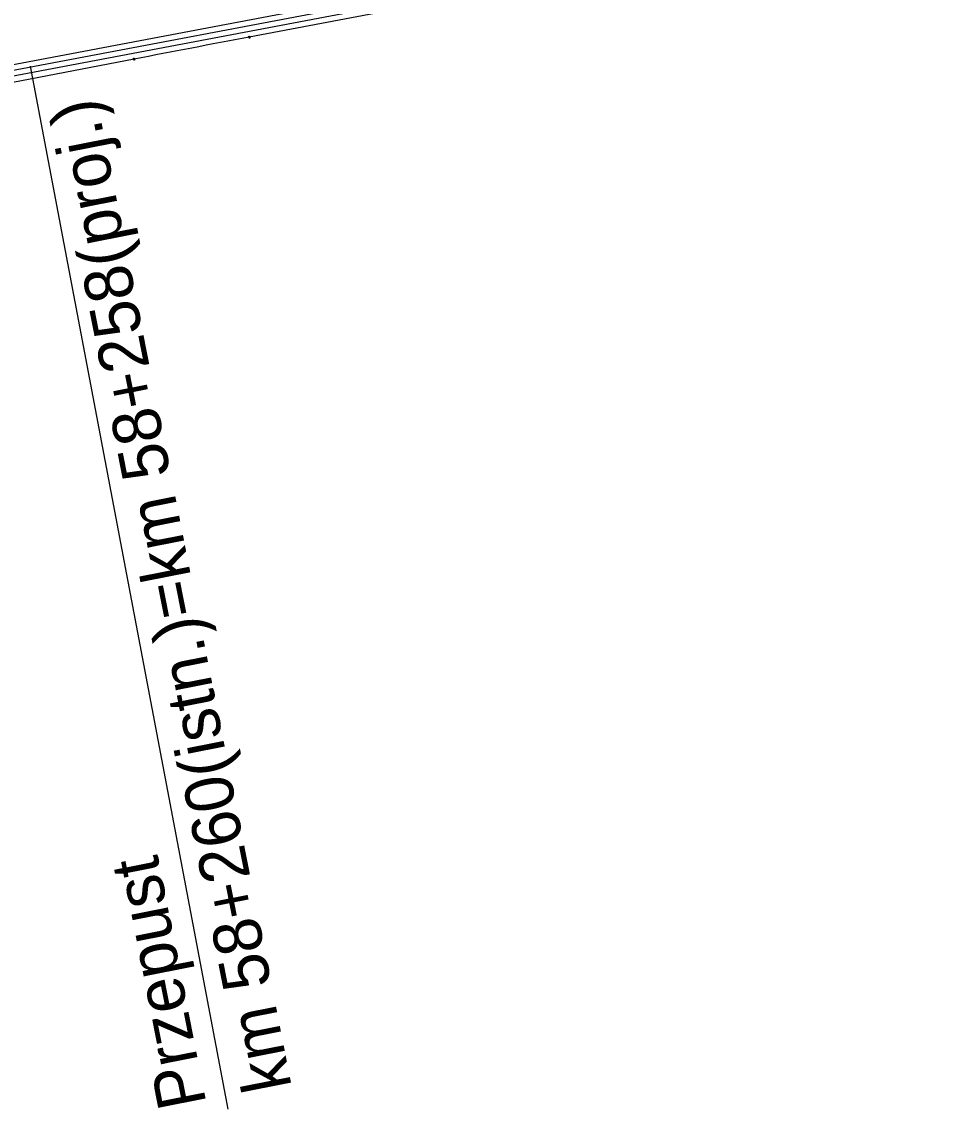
# Model space of a CAD drawing. Extents: x 6540402 to 6566579, y 5525343 to 5532423.
# Drawn here: x 6560773 to 6561436, y 5528558 to 5529347 of the extents above; entities that cross this region are included whole.
import ezdxf

# ---------------------------------------------------------------- set-up
doc = ezdxf.new("R2010")
doc.units = 0
for name, color, linetype in [('IR_ps_geometria', 7, 'Continuous'), ('TOR_PS_OPIS_T-opisy dodatkowe', 7, 'Continuous'), ('TOR_PS_T-tory projektowane', 7, 'Continuous')]:
    doc.layers.add(name, color=color, linetype=linetype)

msp = doc.modelspace()

# ---------------------------------------------------------------- linework, layer by layer
at = {"layer": 'IR_ps_geometria'}
for points in [[(6560937.83, 5529335.95), (6560937.87, 5529335.71), (6560937.9, 5529335.71), (6560937.94, 5529335.71), (6560937.97, 5529335.7), (6560938, 5529335.7), (6560938.03, 5529335.68), (6560938.06, 5529335.67), (6560938.09, 5529335.65), (6560938.11, 5529335.62), (6560938.13, 5529335.6), (6560938.14, 5529335.57), (6560938.16, 5529335.54), (6560938.16, 5529335.51), (6560938.17, 5529335.47), (6560938.17, 5529335.44), (6560938.16, 5529335.41), (6560938.15, 5529335.38), (6560938.14, 5529335.35), (6560938.13, 5529335.32), (6560938.1, 5529335.29), (6560938.08, 5529335.27), (6560938.06, 5529335.25), (6560938.03, 5529335.23), (6560938, 5529335.22), (6560937.97, 5529335.21), (6560937.93, 5529335.21), (6560937.9, 5529335.21), (6560937.87, 5529335.22), (6560937.84, 5529335.22), (6560937.81, 5529335.24), (6560937.78, 5529335.25), (6560937.75, 5529335.27), (6560937.73, 5529335.3), (6560937.71, 5529335.32), (6560937.69, 5529335.35), (6560937.68, 5529335.38), (6560937.67, 5529335.41), (6560937.67, 5529335.45), (6560937.67, 5529335.48), (6560937.67, 5529335.51), (6560937.68, 5529335.54), (6560937.7, 5529335.57), (6560937.71, 5529335.6), (6560937.73, 5529335.63), (6560937.76, 5529335.65), (6560937.78, 5529335.67), (6560937.81, 5529335.69), (6560937.84, 5529335.7), (6560937.87, 5529335.71), (6560937.78, 5529336.2), (6560937.75, 5529336.19), (6560937.71, 5529336.19), (6560937.68, 5529336.2), (6560937.65, 5529336.21), (6560937.62, 5529336.22), (6560937.59, 5529336.24), (6560937.57, 5529336.26), (6560937.54, 5529336.28), (6560937.52, 5529336.31), (6560937.51, 5529336.33), (6560937.49, 5529336.36), (6560937.49, 5529336.4), (6560937.48, 5529336.43), (6560937.48, 5529336.46), (6560937.49, 5529336.49), (6560937.5, 5529336.52), (6560937.51, 5529336.55), (6560937.53, 5529336.58), (6560937.55, 5529336.61), (6560937.57, 5529336.63), (6560937.6, 5529336.65), (6560937.62, 5529336.67), (6560937.65, 5529336.68), (6560937.69, 5529336.69), (6560937.72, 5529336.69), (6560937.75, 5529336.69), (6560937.78, 5529336.69), (6560937.81, 5529336.68), (6560937.84, 5529336.67), (6560937.87, 5529336.65), (6560937.9, 5529336.63), (6560937.92, 5529336.61), (6560937.94, 5529336.58), (6560937.96, 5529336.55), (6560937.97, 5529336.52), (6560937.98, 5529336.49), (6560937.98, 5529336.46), (6560937.98, 5529336.42), (6560937.98, 5529336.39), (6560937.97, 5529336.36), (6560937.96, 5529336.33), (6560937.94, 5529336.3), (6560937.92, 5529336.28), (6560937.9, 5529336.25), (6560937.87, 5529336.23), (6560937.84, 5529336.22), (6560937.81, 5529336.2), (6560937.78, 5529336.2)], [(6560937.83, 5529335.95), (6560937.87, 5529335.71), (6560937.9, 5529335.71), (6560937.94, 5529335.71), (6560937.97, 5529335.7), (6560938, 5529335.7), (6560938.03, 5529335.68), (6560938.06, 5529335.67), (6560938.09, 5529335.65), (6560938.11, 5529335.62), (6560938.13, 5529335.6), (6560938.14, 5529335.57), (6560938.16, 5529335.54), (6560938.16, 5529335.51), (6560938.17, 5529335.47), (6560938.17, 5529335.44), (6560938.16, 5529335.41), (6560938.15, 5529335.38), (6560938.14, 5529335.35), (6560938.13, 5529335.32), (6560938.1, 5529335.29), (6560938.08, 5529335.27), (6560938.06, 5529335.25), (6560938.03, 5529335.23), (6560938, 5529335.22), (6560937.97, 5529335.21), (6560937.93, 5529335.21), (6560937.9, 5529335.21), (6560937.87, 5529335.22), (6560937.84, 5529335.22), (6560937.81, 5529335.24), (6560937.78, 5529335.25), (6560937.75, 5529335.27), (6560937.73, 5529335.3), (6560937.71, 5529335.32), (6560937.69, 5529335.35), (6560937.68, 5529335.38), (6560937.67, 5529335.41), (6560937.67, 5529335.45), (6560937.67, 5529335.48), (6560937.67, 5529335.51), (6560937.68, 5529335.54), (6560937.7, 5529335.57), (6560937.71, 5529335.6), (6560937.73, 5529335.63), (6560937.76, 5529335.65), (6560937.78, 5529335.67), (6560937.81, 5529335.69), (6560937.84, 5529335.7), (6560937.87, 5529335.71), (6560937.78, 5529336.2), (6560937.75, 5529336.19), (6560937.71, 5529336.19), (6560937.68, 5529336.2), (6560937.65, 5529336.21), (6560937.62, 5529336.22), (6560937.59, 5529336.24), (6560937.57, 5529336.26), (6560937.54, 5529336.28), (6560937.52, 5529336.31), (6560937.51, 5529336.33), (6560937.49, 5529336.36), (6560937.49, 5529336.4), (6560937.48, 5529336.43), (6560937.48, 5529336.46), (6560937.49, 5529336.49), (6560937.5, 5529336.52), (6560937.51, 5529336.55), (6560937.53, 5529336.58), (6560937.55, 5529336.61), (6560937.57, 5529336.63), (6560937.6, 5529336.65), (6560937.62, 5529336.67), (6560937.65, 5529336.68), (6560937.69, 5529336.69), (6560937.72, 5529336.69), (6560937.75, 5529336.69), (6560937.78, 5529336.69), (6560937.81, 5529336.68), (6560937.84, 5529336.67), (6560937.87, 5529336.65), (6560937.9, 5529336.63), (6560937.92, 5529336.61), (6560937.94, 5529336.58), (6560937.96, 5529336.55), (6560937.97, 5529336.52), (6560937.98, 5529336.49), (6560937.98, 5529336.46), (6560937.98, 5529336.42), (6560937.98, 5529336.39), (6560937.97, 5529336.36), (6560937.96, 5529336.33), (6560937.94, 5529336.3), (6560937.92, 5529336.28), (6560937.9, 5529336.25), (6560937.87, 5529336.23), (6560937.84, 5529336.22), (6560937.81, 5529336.2), (6560937.78, 5529336.2)], [(6560937.83, 5529335.95), (6560937.87, 5529335.71), (6560937.9, 5529335.71), (6560937.94, 5529335.71), (6560937.97, 5529335.7), (6560938, 5529335.7), (6560938.03, 5529335.68), (6560938.06, 5529335.67), (6560938.09, 5529335.65), (6560938.11, 5529335.62), (6560938.13, 5529335.6), (6560938.14, 5529335.57), (6560938.16, 5529335.54), (6560938.16, 5529335.51), (6560938.17, 5529335.47), (6560938.17, 5529335.44), (6560938.16, 5529335.41), (6560938.15, 5529335.38), (6560938.14, 5529335.35), (6560938.13, 5529335.32), (6560938.1, 5529335.29), (6560938.08, 5529335.27), (6560938.06, 5529335.25), (6560938.03, 5529335.23), (6560938, 5529335.22), (6560937.97, 5529335.21), (6560937.93, 5529335.21), (6560937.9, 5529335.21), (6560937.87, 5529335.22), (6560937.84, 5529335.22), (6560937.81, 5529335.24), (6560937.78, 5529335.25), (6560937.75, 5529335.27), (6560937.73, 5529335.3), (6560937.71, 5529335.32), (6560937.69, 5529335.35), (6560937.68, 5529335.38), (6560937.67, 5529335.41), (6560937.67, 5529335.45), (6560937.67, 5529335.48), (6560937.67, 5529335.51), (6560937.68, 5529335.54), (6560937.7, 5529335.57), (6560937.71, 5529335.6), (6560937.73, 5529335.63), (6560937.76, 5529335.65), (6560937.78, 5529335.67), (6560937.81, 5529335.69), (6560937.84, 5529335.7), (6560937.87, 5529335.71), (6560937.78, 5529336.2), (6560937.75, 5529336.19), (6560937.71, 5529336.19), (6560937.68, 5529336.2), (6560937.65, 5529336.21), (6560937.62, 5529336.22), (6560937.59, 5529336.24), (6560937.57, 5529336.26), (6560937.54, 5529336.28), (6560937.52, 5529336.31), (6560937.51, 5529336.33), (6560937.49, 5529336.36), (6560937.49, 5529336.4), (6560937.48, 5529336.43), (6560937.48, 5529336.46), (6560937.49, 5529336.49), (6560937.5, 5529336.52), (6560937.51, 5529336.55), (6560937.53, 5529336.58), (6560937.55, 5529336.61), (6560937.57, 5529336.63), (6560937.6, 5529336.65), (6560937.62, 5529336.67), (6560937.65, 5529336.68), (6560937.69, 5529336.69), (6560937.72, 5529336.69), (6560937.75, 5529336.69), (6560937.78, 5529336.69), (6560937.81, 5529336.68), (6560937.84, 5529336.67), (6560937.87, 5529336.65), (6560937.9, 5529336.63), (6560937.92, 5529336.61), (6560937.94, 5529336.58), (6560937.96, 5529336.55), (6560937.97, 5529336.52), (6560937.98, 5529336.49), (6560937.98, 5529336.46), (6560937.98, 5529336.42), (6560937.98, 5529336.39), (6560937.97, 5529336.36), (6560937.96, 5529336.33), (6560937.94, 5529336.3), (6560937.92, 5529336.28), (6560937.9, 5529336.25), (6560937.87, 5529336.23), (6560937.84, 5529336.22), (6560937.81, 5529336.2), (6560937.78, 5529336.2)], [(6560937.83, 5529335.95), (6560937.87, 5529335.71), (6560937.9, 5529335.71), (6560937.94, 5529335.71), (6560937.97, 5529335.7), (6560938, 5529335.7), (6560938.03, 5529335.68), (6560938.06, 5529335.67), (6560938.09, 5529335.65), (6560938.11, 5529335.62), (6560938.13, 5529335.6), (6560938.14, 5529335.57), (6560938.16, 5529335.54), (6560938.16, 5529335.51), (6560938.17, 5529335.47), (6560938.17, 5529335.44), (6560938.16, 5529335.41), (6560938.15, 5529335.38), (6560938.14, 5529335.35), (6560938.13, 5529335.32), (6560938.1, 5529335.29), (6560938.08, 5529335.27), (6560938.06, 5529335.25), (6560938.03, 5529335.23), (6560938, 5529335.22), (6560937.97, 5529335.21), (6560937.93, 5529335.21), (6560937.9, 5529335.21), (6560937.87, 5529335.22), (6560937.84, 5529335.22), (6560937.81, 5529335.24), (6560937.78, 5529335.25), (6560937.75, 5529335.27), (6560937.73, 5529335.3), (6560937.71, 5529335.32), (6560937.69, 5529335.35), (6560937.68, 5529335.38), (6560937.67, 5529335.41), (6560937.67, 5529335.45), (6560937.67, 5529335.48), (6560937.67, 5529335.51), (6560937.68, 5529335.54), (6560937.7, 5529335.57), (6560937.71, 5529335.6), (6560937.73, 5529335.63), (6560937.76, 5529335.65), (6560937.78, 5529335.67), (6560937.81, 5529335.69), (6560937.84, 5529335.7), (6560937.87, 5529335.71), (6560937.78, 5529336.2), (6560937.75, 5529336.19), (6560937.71, 5529336.19), (6560937.68, 5529336.2), (6560937.65, 5529336.21), (6560937.62, 5529336.22), (6560937.59, 5529336.24), (6560937.57, 5529336.26), (6560937.54, 5529336.28), (6560937.52, 5529336.31), (6560937.51, 5529336.33), (6560937.49, 5529336.36), (6560937.49, 5529336.4), (6560937.48, 5529336.43), (6560937.48, 5529336.46), (6560937.49, 5529336.49), (6560937.5, 5529336.52), (6560937.51, 5529336.55), (6560937.53, 5529336.58), (6560937.55, 5529336.61), (6560937.57, 5529336.63), (6560937.6, 5529336.65), (6560937.62, 5529336.67), (6560937.65, 5529336.68), (6560937.69, 5529336.69), (6560937.72, 5529336.69), (6560937.75, 5529336.69), (6560937.78, 5529336.69), (6560937.81, 5529336.68), (6560937.84, 5529336.67), (6560937.87, 5529336.65), (6560937.9, 5529336.63), (6560937.92, 5529336.61), (6560937.94, 5529336.58), (6560937.96, 5529336.55), (6560937.97, 5529336.52), (6560937.98, 5529336.49), (6560937.98, 5529336.46), (6560937.98, 5529336.42), (6560937.98, 5529336.39), (6560937.97, 5529336.36), (6560937.96, 5529336.33), (6560937.94, 5529336.3), (6560937.92, 5529336.28), (6560937.9, 5529336.25), (6560937.87, 5529336.23), (6560937.84, 5529336.22), (6560937.81, 5529336.2), (6560937.78, 5529336.2)], [(6560854.33, 5529320.01), (6560854.38, 5529319.77), (6560854.41, 5529319.77), (6560854.45, 5529319.77), (6560854.48, 5529319.77), (6560854.51, 5529319.76), (6560854.54, 5529319.75), (6560854.57, 5529319.73), (6560854.59, 5529319.71), (6560854.62, 5529319.69), (6560854.64, 5529319.66), (6560854.65, 5529319.63), (6560854.67, 5529319.6), (6560854.67, 5529319.57), (6560854.68, 5529319.54), (6560854.68, 5529319.5), (6560854.67, 5529319.47), (6560854.66, 5529319.44), (6560854.65, 5529319.41), (6560854.63, 5529319.38), (6560854.61, 5529319.36), (6560854.59, 5529319.33), (6560854.57, 5529319.31), (6560854.54, 5529319.3), (6560854.51, 5529319.29), (6560854.48, 5529319.28), (6560854.44, 5529319.27), (6560854.41, 5529319.27), (6560854.38, 5529319.28), (6560854.35, 5529319.29), (6560854.32, 5529319.3), (6560854.29, 5529319.32), (6560854.26, 5529319.34), (6560854.24, 5529319.36), (6560854.22, 5529319.38), (6560854.2, 5529319.41), (6560854.19, 5529319.44), (6560854.18, 5529319.48), (6560854.18, 5529319.51), (6560854.18, 5529319.54), (6560854.18, 5529319.57), (6560854.19, 5529319.6), (6560854.2, 5529319.63), (6560854.22, 5529319.66), (6560854.24, 5529319.69), (6560854.26, 5529319.71), (6560854.29, 5529319.73), (6560854.32, 5529319.75), (6560854.35, 5529319.76), (6560854.38, 5529319.77), (6560854.29, 5529320.26), (6560854.25, 5529320.25), (6560854.22, 5529320.26), (6560854.19, 5529320.26), (6560854.16, 5529320.27), (6560854.13, 5529320.28), (6560854.1, 5529320.3), (6560854.07, 5529320.32), (6560854.05, 5529320.34), (6560854.03, 5529320.37), (6560854.01, 5529320.4), (6560854, 5529320.43), (6560853.99, 5529320.46), (6560853.99, 5529320.49), (6560853.99, 5529320.52), (6560853.99, 5529320.55), (6560854, 5529320.59), (6560854.02, 5529320.62), (6560854.03, 5529320.64), (6560854.05, 5529320.67), (6560854.08, 5529320.69), (6560854.1, 5529320.71), (6560854.13, 5529320.73), (6560854.16, 5529320.74), (6560854.19, 5529320.75), (6560854.22, 5529320.75), (6560854.26, 5529320.75), (6560854.29, 5529320.75), (6560854.32, 5529320.74), (6560854.35, 5529320.73), (6560854.38, 5529320.71), (6560854.41, 5529320.69), (6560854.43, 5529320.67), (6560854.45, 5529320.64), (6560854.46, 5529320.61), (6560854.48, 5529320.58), (6560854.48, 5529320.55), (6560854.49, 5529320.52), (6560854.49, 5529320.49), (6560854.48, 5529320.45), (6560854.48, 5529320.42), (6560854.46, 5529320.39), (6560854.45, 5529320.36), (6560854.43, 5529320.34), (6560854.4, 5529320.32), (6560854.38, 5529320.3), (6560854.35, 5529320.28), (6560854.32, 5529320.27), (6560854.29, 5529320.26)], [(6560854.33, 5529320.01), (6560854.38, 5529319.77), (6560854.41, 5529319.77), (6560854.45, 5529319.77), (6560854.48, 5529319.77), (6560854.51, 5529319.76), (6560854.54, 5529319.75), (6560854.57, 5529319.73), (6560854.59, 5529319.71), (6560854.62, 5529319.69), (6560854.64, 5529319.66), (6560854.65, 5529319.63), (6560854.67, 5529319.6), (6560854.67, 5529319.57), (6560854.68, 5529319.54), (6560854.68, 5529319.5), (6560854.67, 5529319.47), (6560854.66, 5529319.44), (6560854.65, 5529319.41), (6560854.63, 5529319.38), (6560854.61, 5529319.36), (6560854.59, 5529319.33), (6560854.57, 5529319.31), (6560854.54, 5529319.3), (6560854.51, 5529319.29), (6560854.48, 5529319.28), (6560854.44, 5529319.27), (6560854.41, 5529319.27), (6560854.38, 5529319.28), (6560854.35, 5529319.29), (6560854.32, 5529319.3), (6560854.29, 5529319.32), (6560854.26, 5529319.34), (6560854.24, 5529319.36), (6560854.22, 5529319.38), (6560854.2, 5529319.41), (6560854.19, 5529319.44), (6560854.18, 5529319.48), (6560854.18, 5529319.51), (6560854.18, 5529319.54), (6560854.18, 5529319.57), (6560854.19, 5529319.6), (6560854.2, 5529319.63), (6560854.22, 5529319.66), (6560854.24, 5529319.69), (6560854.26, 5529319.71), (6560854.29, 5529319.73), (6560854.32, 5529319.75), (6560854.35, 5529319.76), (6560854.38, 5529319.77), (6560854.29, 5529320.26), (6560854.25, 5529320.25), (6560854.22, 5529320.26), (6560854.19, 5529320.26), (6560854.16, 5529320.27), (6560854.13, 5529320.28), (6560854.1, 5529320.3), (6560854.07, 5529320.32), (6560854.05, 5529320.34), (6560854.03, 5529320.37), (6560854.01, 5529320.4), (6560854, 5529320.43), (6560853.99, 5529320.46), (6560853.99, 5529320.49), (6560853.99, 5529320.52), (6560853.99, 5529320.55), (6560854, 5529320.59), (6560854.02, 5529320.62), (6560854.03, 5529320.64), (6560854.05, 5529320.67), (6560854.08, 5529320.69), (6560854.1, 5529320.71), (6560854.13, 5529320.73), (6560854.16, 5529320.74), (6560854.19, 5529320.75), (6560854.22, 5529320.75), (6560854.26, 5529320.75), (6560854.29, 5529320.75), (6560854.32, 5529320.74), (6560854.35, 5529320.73), (6560854.38, 5529320.71), (6560854.41, 5529320.69), (6560854.43, 5529320.67), (6560854.45, 5529320.64), (6560854.46, 5529320.61), (6560854.48, 5529320.58), (6560854.48, 5529320.55), (6560854.49, 5529320.52), (6560854.49, 5529320.49), (6560854.48, 5529320.45), (6560854.48, 5529320.42), (6560854.46, 5529320.39), (6560854.45, 5529320.36), (6560854.43, 5529320.34), (6560854.4, 5529320.32), (6560854.38, 5529320.3), (6560854.35, 5529320.28), (6560854.32, 5529320.27), (6560854.29, 5529320.26)], [(6560854.33, 5529320.01), (6560854.38, 5529319.77), (6560854.41, 5529319.77), (6560854.45, 5529319.77), (6560854.48, 5529319.77), (6560854.51, 5529319.76), (6560854.54, 5529319.75), (6560854.57, 5529319.73), (6560854.59, 5529319.71), (6560854.62, 5529319.69), (6560854.64, 5529319.66), (6560854.65, 5529319.63), (6560854.67, 5529319.6), (6560854.67, 5529319.57), (6560854.68, 5529319.54), (6560854.68, 5529319.5), (6560854.67, 5529319.47), (6560854.66, 5529319.44), (6560854.65, 5529319.41), (6560854.63, 5529319.38), (6560854.61, 5529319.36), (6560854.59, 5529319.33), (6560854.57, 5529319.31), (6560854.54, 5529319.3), (6560854.51, 5529319.29), (6560854.48, 5529319.28), (6560854.44, 5529319.27), (6560854.41, 5529319.27), (6560854.38, 5529319.28), (6560854.35, 5529319.29), (6560854.32, 5529319.3), (6560854.29, 5529319.32), (6560854.26, 5529319.34), (6560854.24, 5529319.36), (6560854.22, 5529319.38), (6560854.2, 5529319.41), (6560854.19, 5529319.44), (6560854.18, 5529319.48), (6560854.18, 5529319.51), (6560854.18, 5529319.54), (6560854.18, 5529319.57), (6560854.19, 5529319.6), (6560854.2, 5529319.63), (6560854.22, 5529319.66), (6560854.24, 5529319.69), (6560854.26, 5529319.71), (6560854.29, 5529319.73), (6560854.32, 5529319.75), (6560854.35, 5529319.76), (6560854.38, 5529319.77), (6560854.29, 5529320.26), (6560854.25, 5529320.25), (6560854.22, 5529320.26), (6560854.19, 5529320.26), (6560854.16, 5529320.27), (6560854.13, 5529320.28), (6560854.1, 5529320.3), (6560854.07, 5529320.32), (6560854.05, 5529320.34), (6560854.03, 5529320.37), (6560854.01, 5529320.4), (6560854, 5529320.43), (6560853.99, 5529320.46), (6560853.99, 5529320.49), (6560853.99, 5529320.52), (6560853.99, 5529320.55), (6560854, 5529320.59), (6560854.02, 5529320.62), (6560854.03, 5529320.64), (6560854.05, 5529320.67), (6560854.08, 5529320.69), (6560854.1, 5529320.71), (6560854.13, 5529320.73), (6560854.16, 5529320.74), (6560854.19, 5529320.75), (6560854.22, 5529320.75), (6560854.26, 5529320.75), (6560854.29, 5529320.75), (6560854.32, 5529320.74), (6560854.35, 5529320.73), (6560854.38, 5529320.71), (6560854.41, 5529320.69), (6560854.43, 5529320.67), (6560854.45, 5529320.64), (6560854.46, 5529320.61), (6560854.48, 5529320.58), (6560854.48, 5529320.55), (6560854.49, 5529320.52), (6560854.49, 5529320.49), (6560854.48, 5529320.45), (6560854.48, 5529320.42), (6560854.46, 5529320.39), (6560854.45, 5529320.36), (6560854.43, 5529320.34), (6560854.4, 5529320.32), (6560854.38, 5529320.3), (6560854.35, 5529320.28), (6560854.32, 5529320.27), (6560854.29, 5529320.26)], [(6560854.33, 5529320.01), (6560854.38, 5529319.77), (6560854.41, 5529319.77), (6560854.45, 5529319.77), (6560854.48, 5529319.77), (6560854.51, 5529319.76), (6560854.54, 5529319.75), (6560854.57, 5529319.73), (6560854.59, 5529319.71), (6560854.62, 5529319.69), (6560854.64, 5529319.66), (6560854.65, 5529319.63), (6560854.67, 5529319.6), (6560854.67, 5529319.57), (6560854.68, 5529319.54), (6560854.68, 5529319.5), (6560854.67, 5529319.47), (6560854.66, 5529319.44), (6560854.65, 5529319.41), (6560854.63, 5529319.38), (6560854.61, 5529319.36), (6560854.59, 5529319.33), (6560854.57, 5529319.31), (6560854.54, 5529319.3), (6560854.51, 5529319.29), (6560854.48, 5529319.28), (6560854.44, 5529319.27), (6560854.41, 5529319.27), (6560854.38, 5529319.28), (6560854.35, 5529319.29), (6560854.32, 5529319.3), (6560854.29, 5529319.32), (6560854.26, 5529319.34), (6560854.24, 5529319.36), (6560854.22, 5529319.38), (6560854.2, 5529319.41), (6560854.19, 5529319.44), (6560854.18, 5529319.48), (6560854.18, 5529319.51), (6560854.18, 5529319.54), (6560854.18, 5529319.57), (6560854.19, 5529319.6), (6560854.2, 5529319.63), (6560854.22, 5529319.66), (6560854.24, 5529319.69), (6560854.26, 5529319.71), (6560854.29, 5529319.73), (6560854.32, 5529319.75), (6560854.35, 5529319.76), (6560854.38, 5529319.77), (6560854.29, 5529320.26), (6560854.25, 5529320.25), (6560854.22, 5529320.26), (6560854.19, 5529320.26), (6560854.16, 5529320.27), (6560854.13, 5529320.28), (6560854.1, 5529320.3), (6560854.07, 5529320.32), (6560854.05, 5529320.34), (6560854.03, 5529320.37), (6560854.01, 5529320.4), (6560854, 5529320.43), (6560853.99, 5529320.46), (6560853.99, 5529320.49), (6560853.99, 5529320.52), (6560853.99, 5529320.55), (6560854, 5529320.59), (6560854.02, 5529320.62), (6560854.03, 5529320.64), (6560854.05, 5529320.67), (6560854.08, 5529320.69), (6560854.1, 5529320.71), (6560854.13, 5529320.73), (6560854.16, 5529320.74), (6560854.19, 5529320.75), (6560854.22, 5529320.75), (6560854.26, 5529320.75), (6560854.29, 5529320.75), (6560854.32, 5529320.74), (6560854.35, 5529320.73), (6560854.38, 5529320.71), (6560854.41, 5529320.69), (6560854.43, 5529320.67), (6560854.45, 5529320.64), (6560854.46, 5529320.61), (6560854.48, 5529320.58), (6560854.48, 5529320.55), (6560854.49, 5529320.52), (6560854.49, 5529320.49), (6560854.48, 5529320.45), (6560854.48, 5529320.42), (6560854.46, 5529320.39), (6560854.45, 5529320.36), (6560854.43, 5529320.34), (6560854.4, 5529320.32), (6560854.38, 5529320.3), (6560854.35, 5529320.28), (6560854.32, 5529320.27), (6560854.29, 5529320.26)]]:
    msp.add_lwpolyline(points, close=True, dxfattribs=at)
at = {"layer": 'TOR_PS_OPIS_T-opisy dodatkowe'}
msp.add_line((6560778.99, 5529314.8), (6560922.36, 5528558.42), dxfattribs=at)
at = {"layer": 'TOR_PS_T-tory projektowane'}
for p, q in [((6565849.6, 5530271.11), (6560351.86, 5529229)), ((6565850.35, 5530267.13), (6560937.83, 5529335.95)), ((6563822.31, 5529890.96), (6560454.46, 5529252.57)), ((6562347.76, 5529615.57), (6560501.45, 5529265.6)), ((6560854.33, 5529320.01), (6560766.49, 5529303.13))]:
    msp.add_line(p, q, dxfattribs=at)
msp.add_arc((6567074.32, 5496962.41), 32950, 100.733239, 100.881042, dxfattribs=at)

# ---------------------------------------------------------------- texts
at = {"layer": 'TOR_PS_OPIS_T-opisy dodatkowe'}
for s, p in [('km 58+260(istn.)=km 58+258(proj.)  ', (6560968.68, 5528574.65)), ('Przepust ', (6560906.87, 5528562.46))]:
    msp.add_text(s, height=35, rotation=101.15785, dxfattribs=at).set_placement(p)

doc.saveas('drawing.dxf')
